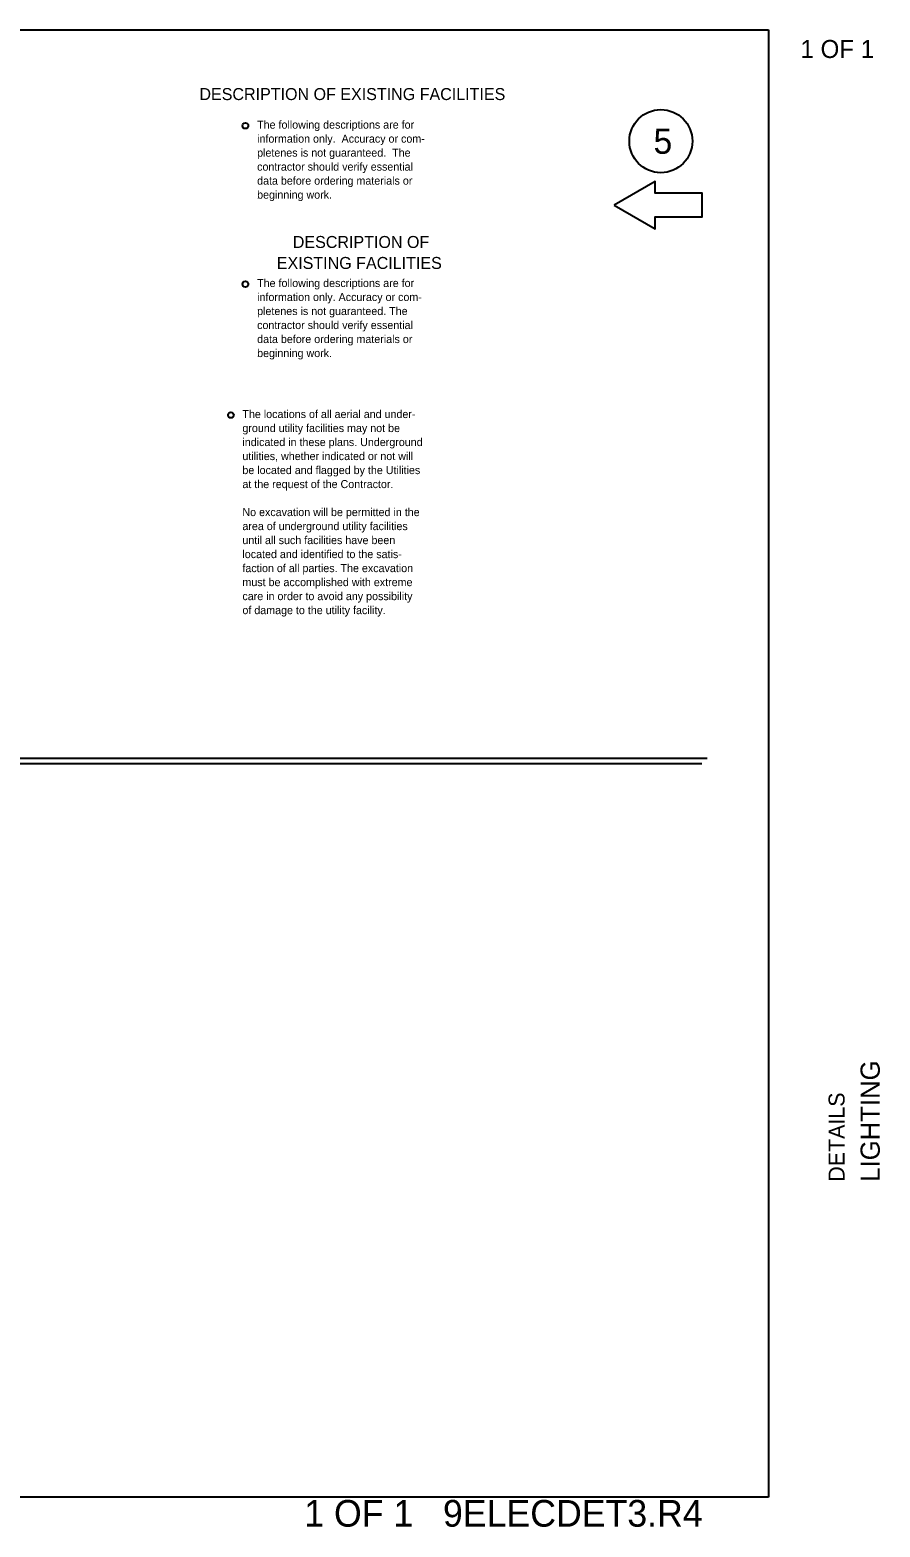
# Model space of a CAD drawing. Extents: x 0.12 to 2.92, y 0.04 to 1.92.
# Drawn here: x 1.859 to 2.921, y 0.045 to 1.915 of the extents above; entities that cross this region are included whole.
import ezdxf

# ---------------------------------------------------------------- set-up
doc = ezdxf.new("R2010")
doc.units = 0
for name, color, linetype in [('Border Active Points', 7, 'Continuous'), ('Border Engr Stamp', 7, 'Continuous'), ('Border Line', 7, 'Continuous'), ('Default', 7, 'Continuous'), ('Notes Engineer Stamps', 7, 'Continuous'), ('Notes Note Guide Cell', 7, 'Continuous')]:
    doc.layers.add(name, color=color, linetype=linetype)

msp = doc.modelspace()

# ---------------------------------------------------------------- linework, layer by layer
at = {"layer": 'Border Active Points'}
for centre, radius in [((2.1278, 1.7955), 0.0036), ((2.1278, 1.5976), 0.0036), ((2.1097, 1.434), 0.00353)]:
    msp.add_circle(centre, radius, dxfattribs=at)
at = {"layer": 'Border Line'}
for p, q in [((0.1984, 0.9987), (2.6984, 0.9987)), ((0.2051, 1.0055), (2.7051, 1.0055))]:
    msp.add_line(p, q, dxfattribs=at)
at = {"layer": 'Default'}
for p, q in [((0.1152, 1.9152), (2.7816, 1.9152)), ((2.7816, 1.9152), (2.7816, 1.9152)), ((2.7816, 1.9152), (2.7816, 0.0822)), ((2.7816, 0.0822), (2.7816, 0.0822))]:
    msp.add_line(p, q, dxfattribs=at)
msp.add_lwpolyline([(2.7816, 0.0822), (2.7816, 0.0822), (0.1152, 0.0822)], dxfattribs=at)
at = {"layer": 'Notes Engineer Stamps'}
msp.add_lwpolyline([(2.5886, 1.6964), (2.6398, 1.6669), (2.6398, 1.6816), (2.6989, 1.6816), (2.6989, 1.7112), (2.6398, 1.7112), (2.6398, 1.726)], close=True, dxfattribs=at)
msp.add_circle((2.6471, 1.7763), 0.0394, dxfattribs=at)

# ---------------------------------------------------------------- texts
at = {"layer": 'Border Active Points'}
for s, p in [('The following descriptions are for', (2.1425, 1.7919)), ('information only.  Accuracy or com-', (2.1425, 1.7744)), ('pletenes is not guaranteed.  The', (2.1425, 1.7569)), ('contractor should verify essential', (2.1425, 1.7394)), ('data before ordering materials or', (2.1425, 1.7219)), ('beginning work.', (2.1425, 1.7044)), ('The following descriptions are for', (2.1425, 1.594)), ('information only. Accuracy or com-', (2.1425, 1.5765)), ('pletenes is not guaranteed. The', (2.1425, 1.559)), ('contractor should verify essential', (2.1425, 1.5415)), ('data before ordering materials or', (2.1425, 1.524)), ('beginning work.', (2.1425, 1.5065)), ('The locations of all aerial and under-', (2.1241, 1.4303)), ('ground utility facilities may not be', (2.1241, 1.4128)), ('indicated in these plans. Underground', (2.1241, 1.3953)), ('utilities, whether indicated or not will', (2.1241, 1.3778)), ('be located and flagged by the Utilities', (2.1241, 1.3603)), ('at the request of the Contractor.', (2.1241, 1.3428)), ('No excavation will be permitted in the', (2.1241, 1.3078)), ('area of underground utility facilities', (2.1241, 1.2903)), ('until all such facilities have been', (2.1241, 1.2728)), ('located and identified to the satis-', (2.1241, 1.2553)), ('faction of all parties. The excavation', (2.1241, 1.2378)), ('must be accomplished with extreme', (2.1241, 1.2203)), ('care in order to avoid any possibility', (2.1241, 1.2028)), ('of damage to the utility facility.', (2.1241, 1.1853))]:
    msp.add_text(s, height=0.01, dxfattribs=at).set_placement(p)
at = {"layer": 'Border Engr Stamp'}
for s, p in [('DESCRIPTION OF EXISTING FACILITIES', (2.0704, 1.8276)), ('DESCRIPTION OF', (2.1871, 1.6428)), ('EXISTING FACILITIES', (2.1671, 1.6166))]:
    msp.add_text(s, height=0.015, dxfattribs=at).set_placement(p)
at = {"layer": 'Notes Engineer Stamps'}
for s, height, p in [('5', 0.0315, (2.6379, 1.7605)), ('1 OF 1   9ELECDET3.R4', 0.033333, (2.2014, 0.0452))]:
    msp.add_text(s, height=height, dxfattribs=at).set_placement(p)
at = {"layer": 'Notes Note Guide Cell'}
msp.add_text('1 OF 1', height=0.0225, dxfattribs=at).set_placement((2.8216, 1.8802))
for s, height, p in [('LIGHTING', 0.024, (2.9207, 0.4762)), ('DETAILS', 0.02, (2.8767, 0.4762))]:
    msp.add_text(s, height=height, rotation=90, dxfattribs=at).set_placement(p)

doc.saveas('drawing.dxf')
